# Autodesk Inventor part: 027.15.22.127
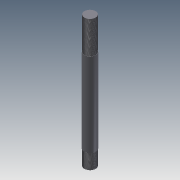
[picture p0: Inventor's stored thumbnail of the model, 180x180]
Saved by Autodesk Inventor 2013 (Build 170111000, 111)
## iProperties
Shininess: 64.0
Length Units: 11269
Angle Units: 11279
Time Units: 11290
Mass Units: 11283
Length Display Precision: 3
Angle Display Precision: 2
Created: 2002-02
Part Number: 027.15.22.127
Material: Steel, Mild
Document SubType Name: Modeling
Designer: SOleg
Density: 7.86 g/cm^3
Density: 0.0
Volumn: 0.0
Area: 0.0
PropertySet Name: Model Information
Control State: 0
Master: False
Checked Out: True
Checked Out Date: 2008-10-15
Last Check In Date: 2008-10-15
Author: SOleg
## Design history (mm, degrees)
sketch "Sketch1"
  geometry: C1 r 13.5 at (0, 0)
  constraints: 1 centre point
  dimensions: "d0" = 27 diameter of C1
extrude "Extrusion1" new body sketch "Sketch1" distance "d1" = 78; taper "d2" = 0 deg
sketch "Sketch2"
  geometry: C1 r 13.5 at (0, 0) reference; C2 r 14 at (0, 0)
  constraints: 1 centre point, 1 coincident
  dimensions: "d5" = 28 diameter of C2
extrude "Extrusion2" join sketch "Sketch2" distance "d3" = 201; taper "d4" = 0 deg
sketch "Sketch3"
  geometry: C1 r 14 at (0, 0) reference; C2 r 13.5 at (0, 0)
  constraints: 1 centre point, 1 coincident
  dimensions: "d6" = 27 diameter of C2
extrude "Extrusion3" join sketch "Sketch3" distance "d7" = 36; taper "d8" = 0 deg
thread "Thread1" dims "d9" = 10, "d10" = 0
thread "Thread2" dims "d11" = 10, "d12" = 0
body "Solid1"
